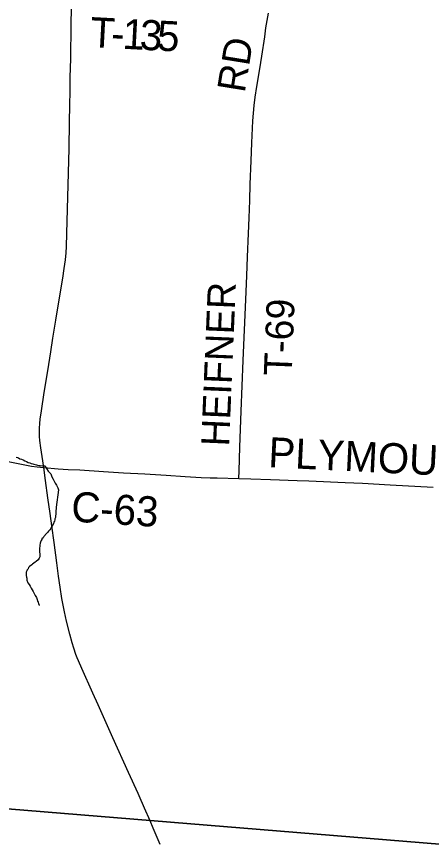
# Model space of a CAD drawing. Extents: x -13.9 to 69.1, y -25.2 to 26.1.
# Drawn here: x 4.329 to 5.08, y 14.961 to 16.445 of the extents above; entities that cross this region are included whole.
import ezdxf

# ---------------------------------------------------------------- set-up
doc = ezdxf.new("R2010")
doc.units = 0
for name, color, linetype in [('GM_X_County_Road', 7, 'Continuous'), ('GM_X_County_Road_Text', 7, 'Continuous'), ('GM_X_Minor_River', 7, 'Continuous'), ('GM_X_State_Route', 7, 'Continuous'), ('GM_X_Township', 7, 'Continuous'), ('GM_X_Township_Road', 7, 'Continuous'), ('GM_X_Township_Road_Text', 7, 'Continuous')]:
    doc.layers.add(name, color=color, linetype=linetype)

msp = doc.modelspace()

# ---------------------------------------------------------------- linework, layer by layer
at = {"layer": 'GM_X_County_Road'}
for points in [[(4.2024, 15.6605), (4.2636, 15.6494), (4.317, 15.6394), (4.3382, 15.6355), (4.3562, 15.6321), (4.3666, 15.6305), (4.3784, 15.6293)], [(4.3784, 15.6293), (4.4046, 15.6271), (4.4223, 15.6261), (4.4433, 15.6251), (4.4863, 15.6224), (4.5227, 15.62), (4.5608, 15.6178), (4.5995, 15.6153), (4.6337, 15.6132), (4.6629, 15.6114), (4.6794, 15.6107), (4.6916, 15.6105), (4.7312, 15.6097)], [(4.7312, 15.6097), (4.7529, 15.6092), (4.7883, 15.6079), (4.8364, 15.6061), (4.8579, 15.6052), (4.9231, 15.6023), (4.9546, 15.6009), (5.0048, 15.5981), (5.0826, 15.5941)]]:
    msp.add_lwpolyline(points, dxfattribs=at)
at = {"layer": 'GM_X_Minor_River'}
for points in [[(4.3283, 15.6484), (4.3307, 15.6477), (4.3327, 15.6469), (4.335, 15.6454), (4.3381, 15.6443), (4.3408, 15.6432), (4.3438, 15.6417), (4.3471, 15.6402), (4.3502, 15.6387), (4.3529, 15.6376), (4.3552, 15.6365), (4.3586, 15.6361), (4.3606, 15.6353), (4.3629, 15.6346), (4.3653, 15.6342), (4.367, 15.6338), (4.3693, 15.633), (4.3717, 15.633), (4.3758, 15.6326), (4.3791, 15.6325), (4.3808, 15.6322), (4.3835, 15.6278), (4.3865, 15.623), (4.3891, 15.6197), (4.3908, 15.6182), (4.3928, 15.6127)], [(4.3928, 15.6127), (4.3951, 15.6084), (4.3977, 15.6036), (4.3991, 15.6014), (4.4011, 15.5974), (4.4024, 15.5948), (4.4037, 15.5926), (4.4044, 15.5908), (4.405, 15.589), (4.4008, 15.5575)], [(4.4008, 15.5575), (4.3996, 15.5389), (4.3985, 15.5368), (4.3981, 15.5346), (4.3974, 15.5324), (4.3964, 15.5306), (4.396, 15.5285), (4.3942, 15.5252), (4.3925, 15.5223), (4.3911, 15.5191), (4.3894, 15.5169), (4.3869, 15.5141), (4.3855, 15.5123), (4.3835, 15.5101), (4.3783, 15.5048), (4.3769, 15.5026), (4.3745, 15.5008), (4.3745, 15.499), (4.3734, 15.4972), (4.3724, 15.4947), (4.3716, 15.4925), (4.3709, 15.4889), (4.3709, 15.4867), (4.3708, 15.4841), (4.3708, 15.4805), (4.3707, 15.4783), (4.3707, 15.4765), (4.371, 15.4736), (4.3709, 15.471), (4.3709, 15.4678), (4.3698, 15.4656), (4.3681, 15.4627), (4.3646, 15.4595), (4.3626, 15.4584), (4.3605, 15.4563), (4.3581, 15.4545), (4.3564, 15.4535), (4.3523, 15.4503), (4.3509, 15.4485), (4.3498, 15.4463), (4.3484, 15.4445), (4.3474, 15.4427), (4.3467, 15.4402), (4.3463, 15.4373), (4.3466, 15.434), (4.3472, 15.4314), (4.3478, 15.4296), (4.3478, 15.4259), (4.3497, 15.4208), (4.3521, 15.4179), (4.3534, 15.4149), (4.3553, 15.4112), (4.3573, 15.4086), (4.359, 15.4053), (4.3609, 15.4016), (4.3629, 15.3983), (4.3642, 15.3965), (4.3652, 15.3943), (4.3659, 15.3924), (4.3665, 15.3906), (4.3671, 15.388), (4.3681, 15.3858), (4.3688, 15.3836), (4.3694, 15.3818), (4.3697, 15.3811), (4.3697, 15.3803)]]:
    msp.add_lwpolyline(points, dxfattribs=at)
at = {"layer": 'GM_X_State_Route'}
msp.add_lwpolyline([(4.5889, 14.9481), (4.576, 14.9777), (4.5705, 14.9907), (4.5604, 15.0138), (4.5505, 15.0362), (4.5487, 15.0402), (4.5315, 15.0781), (4.5033, 15.1407), (4.4911, 15.1681), (4.4764, 15.2007), (4.467, 15.2216), (4.447, 15.266), (4.441, 15.28), (4.4388, 15.2854), (4.4365, 15.2914), (4.4327, 15.3026), (4.4295, 15.3128), (4.4253, 15.3281), (4.4195, 15.3517), (4.4155, 15.3684), (4.4131, 15.3806), (4.411, 15.3928), (4.408, 15.4134), (4.4051, 15.4333), (4.4017, 15.4574), (4.3969, 15.494), (4.3928, 15.524), (4.3898, 15.5463), (4.3859, 15.5746), (4.3816, 15.6057), (4.3784, 15.6293), (4.3753, 15.6493), (4.3729, 15.6651), (4.3713, 15.678), (4.3706, 15.6857), (4.3703, 15.6933), (4.3704, 15.7004), (4.371, 15.7087), (4.3719, 15.7169), (4.3739, 15.7316), (4.3793, 15.765), (4.3858, 15.8042), (4.391, 15.8383), (4.3949, 15.8635), (4.4003, 15.8957), (4.4063, 15.9326), (4.4128, 15.9718), (4.4153, 15.9889), (4.4173, 16.0048), (4.4185, 16.0173), (4.4191, 16.0292), (4.4198, 16.0524), (4.4241, 16.2061), (4.4249, 16.2534), (4.4255, 16.2843), (4.4259, 16.3099), (4.4263, 16.3343), (4.427, 16.3688), (4.4281, 16.4288), (4.4287, 16.4609)], dxfattribs=at)
at = {"layer": 'GM_X_Township'}
msp.add_lwpolyline([(1.7571, 14.6812), (1.7571, 14.4145), (6.9888, 14.4145), (6.911, 14.518), (6.8084, 14.4299), (6.5016, 14.8337), (4.1497, 15.026), (3.1986, 15.1105), (3.1977, 15.0965), (3.1593, 14.577), (3.1591, 14.5746), (2.5192, 14.6233)], close=True, dxfattribs=at)
msp.add_lwpolyline([(3.1593, 14.577), (3.1977, 15.0965), (3.1986, 15.1105), (4.1497, 15.026), (6.5016, 14.8337)], dxfattribs=at)
at = {"layer": 'GM_X_Township_Road'}
msp.add_lwpolyline([(4.7312, 15.6097), (4.7316, 15.6237), (4.7327, 15.6659), (4.734, 15.6986), (4.7352, 15.7313), (4.737, 15.777), (4.739, 15.8228), (4.7437, 15.9332), (4.7455, 15.976), (4.7467, 16.0105), (4.7486, 16.0527), (4.7495, 16.0806), (4.7508, 16.1121), (4.7518, 16.1418), (4.7533, 16.184), (4.7546, 16.216), (4.7565, 16.2558), (4.7574, 16.2701), (4.7587, 16.2837), (4.7606, 16.299), (4.7636, 16.3184), (4.7689, 16.35), (4.7725, 16.3728), (4.7778, 16.4081), (4.7801, 16.4239), (4.7845, 16.4509)], dxfattribs=at)

# ---------------------------------------------------------------- texts
at = {"layer": 'GM_X_County_Road_Text'}
for s, height, rotation, p in [('PLYMOUTH', 0.05438, 357.2062, (4.7835, 15.6301)), ('C-63', 0.05437, 356.3122, (4.4267, 15.532))]:
    msp.add_text(s, height=height, rotation=rotation, dxfattribs=at).set_placement(p)
at = {"layer": 'GM_X_Township_Road_Text'}
for s, height, rotation, p in [('T', 0.0544, 357.016, (4.4612, 16.3894)), ('1', 0.0544, 357.0337, (4.5197, 16.3864)), ('3', 0.0544, 357.0606, (4.5509, 16.3848)), ('5', 0.0544, 357.1738, (4.5821, 16.3832)), ('-', 0.0544, 357.0285, (4.499, 16.3875)), ('RD', 0.05066, 80.8233, (4.7416, 16.3055)), ('HEIFNER', 0.05055, 87.5807, (4.7133, 15.667)), ('T-69', 0.05055, 87.7702, (4.8266, 15.7946))]:
    msp.add_text(s, height=height, rotation=rotation, dxfattribs=at).set_placement(p)

doc.saveas('drawing.dxf')
